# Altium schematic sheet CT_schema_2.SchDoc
size 276 x 169 mm
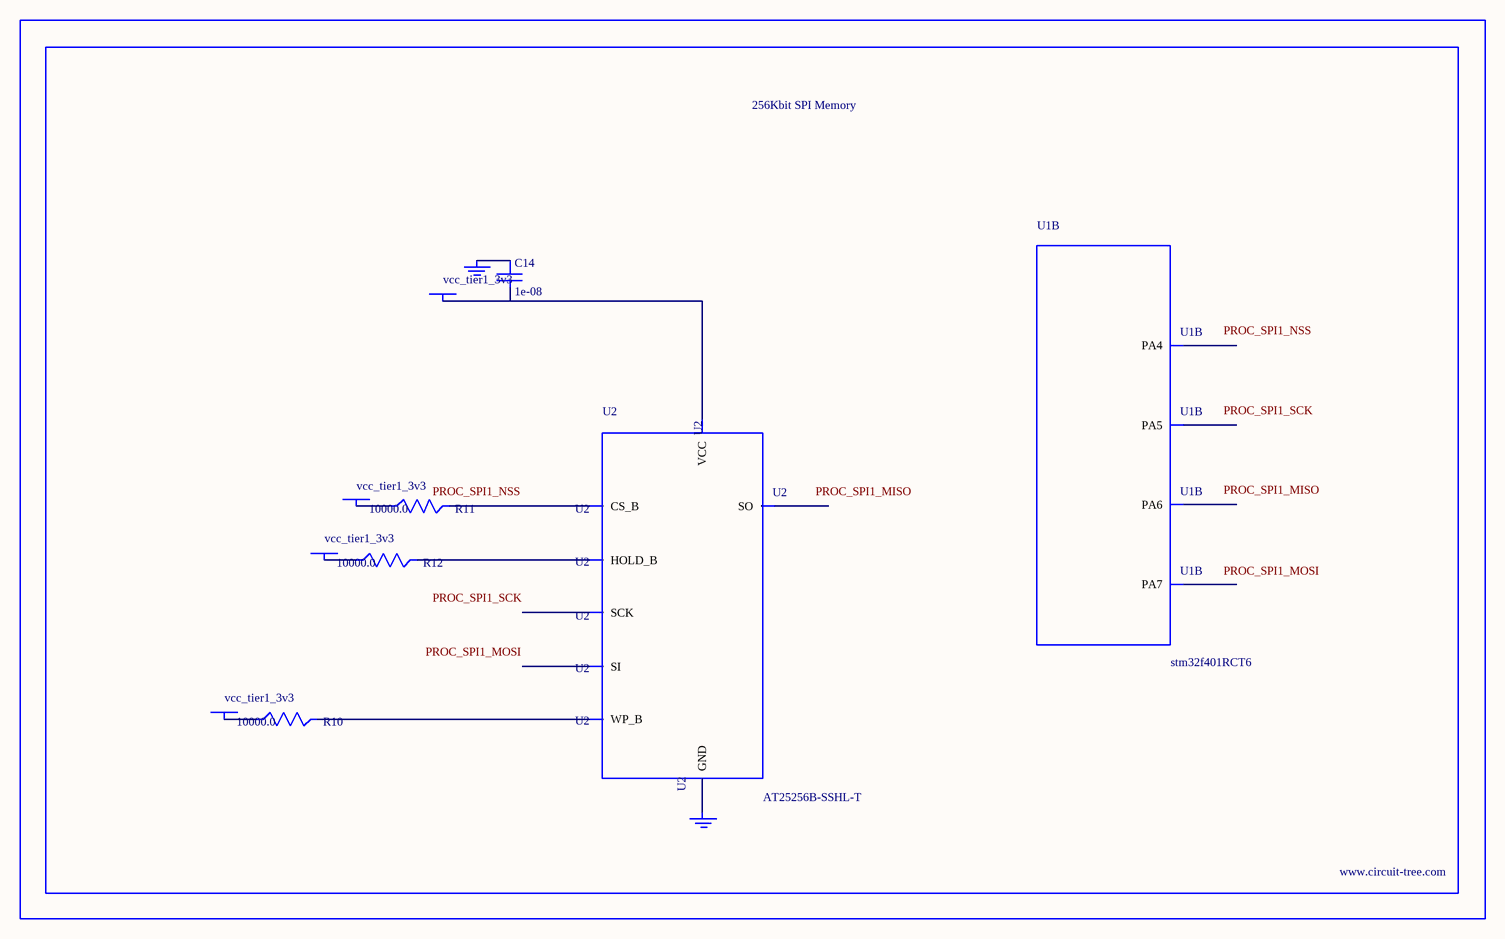
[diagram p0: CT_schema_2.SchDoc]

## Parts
BORDER1  (no value)
C14  1e-08  [C0402]
GND_INSTANCE_1_0  (no value)
GND_INSTANCE_1_1  (no value)
POWER_INSTANCE_1_0  vcc_tier1_3v3
POWER_INSTANCE_1_1  vcc_tier1_3v3
POWER_INSTANCE_1_2  vcc_tier1_3v3
POWER_INSTANCE_1_3  vcc_tier1_3v3
R10  10000.0  [R0603]
R11  10000.0  [R0603]
R12  10000.0  [R0603]
U1  stm32f401RCT6  [LQFP64]  (part B of 9)
U2  AT25256B-SSHL-T  [SOIC-8]

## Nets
NetC14_1: C14.1 GND_INSTANCE_1_0.0(GND)
NetC14_2: C14.2 POWER_INSTANCE_1_3.0(PWR) U2.8(VCC)
NetGND_INSTANCE_1_1_0: GND_INSTANCE_1_1.0(GND) U2.4(GND)
NetPOWER_INSTANCE_1_0_0: POWER_INSTANCE_1_0.0(PWR) R11.1
NetPOWER_INSTANCE_1_1_0: POWER_INSTANCE_1_1.0(PWR) R10.1
NetPOWER_INSTANCE_1_2_0: POWER_INSTANCE_1_2.0(PWR) R12.1
NetR10_2: R10.2 U2.3(WP_B)
NetR11_2: R11.2 U2.1(CS_B)
NetR12_2: R12.2 U2.7(HOLD_B)

Not connected (* = marked no-connect by the designer): U1 20(PA4) 21(PA5) 22(PA6) 23(PA7); U2 2(SO) 5(SI) 6(SCK)

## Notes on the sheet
- Labels drawn without touching a wire or pin: PROC_SPI1_MISO, PROC_SPI1_MOSI, PROC_SPI1_NSS, PROC_SPI1_SCK

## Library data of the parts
BORDER1 = BORDER_PAGE1
C14 = C0402C103K3RAC
GND_INSTANCE_1_0 GND_INSTANCE_1_1 = GND
POWER_INSTANCE_1_0-POWER_INSTANCE_1_3 = PWR
R10-R12 = RC0603JR-0710KL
